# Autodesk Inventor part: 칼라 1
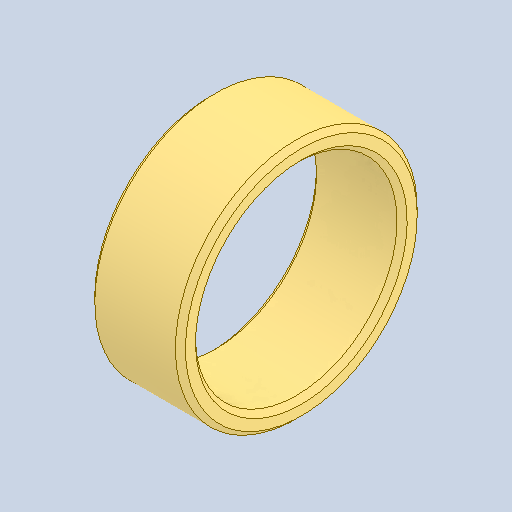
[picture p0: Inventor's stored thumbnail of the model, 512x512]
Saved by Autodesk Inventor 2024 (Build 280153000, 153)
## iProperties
Created: 2025-11
Part Number: 칼라 1
Material: 강철, 연강
Document SubType Name: Modeling
Designer: Edu07
Density: 7.85 g/cm^3
Appearance: 기본값
Author: jhkim
Sending System: Autodesk Inventor 2026
Preprocessor: ST-DEVELOPER v20.1
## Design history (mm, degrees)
node "칼라 11"
node "솔리드2"
node "솔리드1"
